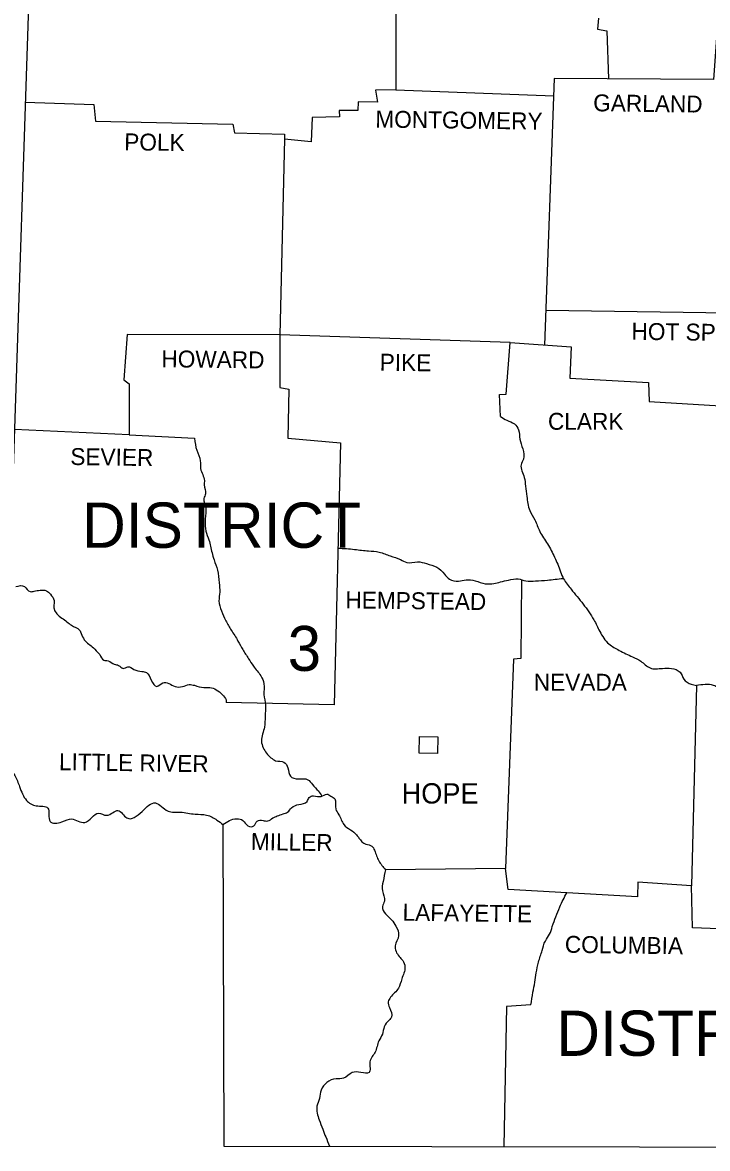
# Model space of a CAD drawing. Extents: x -0.68 to 1.92, y 0 to 0.95.
# Drawn here: x 1.1026 to 1.1814, y 0.5736 to 0.703 of the extents above; entities that cross this region are included whole.
import ezdxf

# ---------------------------------------------------------------- set-up
doc = ezdxf.new("R2010")
doc.units = 0
doc.layers.add('Default', color=7, linetype='Continuous')

msp = doc.modelspace()

# ---------------------------------------------------------------- linework, layer by layer
at = {"layer": 'Default'}
for points in [[(1.09511, 0.81784), (1.10455, 0.74198), (1.10045, 0.61817)], [(1.14558, 0.71393), (1.14552, 0.69525), (1.14321, 0.6952), (1.14342, 0.69385), (1.14122, 0.69387), (1.14116, 0.69286), (1.13901, 0.69286), (1.13906, 0.69216), (1.1359, 0.69206), (1.13582, 0.68928), (1.13274, 0.68957), (1.13222, 0.66711)], [(1.16881, 0.70347), (1.16873, 0.70223), (1.1698, 0.70204), (1.16999, 0.69651)], [(1.19734, 0.70186), (1.18245, 0.7023), (1.18204, 0.69644), (1.16375, 0.69655), (1.16263, 0.66592)], [(1.14552, 0.69525), (1.16368, 0.69454)], [(1.10295, 0.69382), (1.11082, 0.69356), (1.11103, 0.69164), (1.1268, 0.69131), (1.12698, 0.69032), (1.13274, 0.69014), (1.13274, 0.68957)], [(1.16278, 0.66994), (1.18904, 0.66955), (1.18953, 0.67391), (1.19161, 0.67388), (1.19166, 0.67754), (1.20149, 0.67741), (1.20144, 0.6752), (1.20398, 0.67502), (1.20395, 0.67103), (1.20561, 0.67087)], [(1.15867, 0.6662), (1.13222, 0.66711), (1.11466, 0.66714), (1.11427, 0.66192), (1.11489, 0.66148), (1.11487, 0.65562), (1.10171, 0.65622)], [(1.13222, 0.66711), (1.13222, 0.66104), (1.13323, 0.66086), (1.13312, 0.65521), (1.13919, 0.65471), (1.13844, 0.62458), (1.12604, 0.62486)], [(1.15758, 0.65772), (1.15745, 0.66024), (1.1582, 0.66029), (1.15867, 0.6662), (1.16567, 0.66571), (1.16552, 0.66211), (1.17457, 0.66161), (1.17465, 0.65943), (1.18284, 0.65894), (1.18424, 0.65648), (1.18339, 0.65536), (1.1838, 0.65368), (1.2047, 0.65291)], [(1.11487, 0.65562), (1.12241, 0.65521)], [(1.15999, 0.63897), (1.15989, 0.62992), (1.15906, 0.62982), (1.15815, 0.60578)], [(1.18009, 0.62681), (1.1795, 0.60378), (1.17335, 0.60422), (1.1733, 0.60253), (1.16519, 0.603)], [(1.12566, 0.61083), (1.12576, 0.5739), (1.29301, 0.57362)], [(1.16519, 0.603), (1.15846, 0.60339), (1.15815, 0.60578), (1.14433, 0.60565)], [(1.19908, 0.59823), (1.17962, 0.59896), (1.1795, 0.60378)], [(1.16106, 0.59011), (1.15825, 0.58993), (1.15795, 0.57385)]]:
    msp.add_lwpolyline(points, dxfattribs=at)
msp.add_lwpolyline([(1.14822, 0.61903), (1.14827, 0.62097), (1.15037, 0.62092), (1.15032, 0.61898)], close=True, dxfattribs=at)
for points in [[(1.15758, 0.65772), (1.15828, 0.65728), (1.15916, 0.65687), (1.15963, 0.65619), (1.15979, 0.65513), (1.16012, 0.65399), (1.1602, 0.65282), (1.15994, 0.65217), (1.1603, 0.65072), (1.16043, 0.64971), (1.16059, 0.64854), (1.16093, 0.64693), (1.16152, 0.64584), (1.16207, 0.64452), (1.16298, 0.64307), (1.16378, 0.64154), (1.16414, 0.64074), (1.16482, 0.63905), (1.16567, 0.63788), (1.16707, 0.63615), (1.16829, 0.63436), (1.16897, 0.63303), (1.17003, 0.63158), (1.17122, 0.63085), (1.17273, 0.6301), (1.17369, 0.62961), (1.17475, 0.62883), (1.17618, 0.62878), (1.17721, 0.62878), (1.1782, 0.62834), (1.17864, 0.62753), (1.17947, 0.62696), (1.18009, 0.62681)], [(1.12241, 0.65521), (1.12265, 0.65383), (1.12306, 0.65261), (1.12309, 0.65173), (1.12353, 0.65036), (1.1235, 0.64986), (1.12366, 0.64883), (1.12348, 0.64831), (1.12368, 0.64722), (1.12366, 0.64636), (1.12363, 0.64569), (1.12371, 0.64455), (1.12405, 0.64354), (1.12441, 0.64206), (1.12464, 0.64125), (1.12503, 0.64006), (1.12524, 0.63861), (1.12529, 0.63755), (1.12521, 0.63653), (1.1255, 0.63539), (1.12599, 0.63425), (1.12662, 0.63316), (1.12739, 0.63192), (1.12794, 0.63093), (1.12861, 0.62989), (1.12916, 0.62904), (1.13001, 0.62792), (1.13038, 0.62702), (1.13038, 0.62577), (1.13056, 0.62455), (1.13051, 0.62326), (1.13043, 0.62204), (1.13009, 0.62043), (1.1303, 0.61965), (1.13118, 0.61851), (1.13172, 0.61817), (1.13268, 0.61799), (1.13312, 0.61734), (1.13341, 0.61641), (1.13437, 0.61607), (1.13543, 0.61599), (1.13595, 0.61542), (1.13663, 0.6147), (1.13704, 0.61409)], [(1.13889, 0.6426), (1.1408, 0.64245), (1.14241, 0.64227), (1.14363, 0.64214), (1.1449, 0.64169), (1.14607, 0.64128), (1.14679, 0.64094), (1.14801, 0.64102), (1.14907, 0.64081), (1.15024, 0.6404), (1.15112, 0.63962), (1.15169, 0.63902), (1.15273, 0.63879), (1.15361, 0.63895), (1.15465, 0.63884), (1.15582, 0.63851), (1.1568, 0.63853), (1.15758, 0.63871), (1.15849, 0.63892), (1.1596, 0.63905), (1.16046, 0.63884), (1.1616, 0.63882), (1.16295, 0.63892), (1.16478, 0.63912)], [(1.10185, 0.63817), (1.10286, 0.63819), (1.10351, 0.6376), (1.10395, 0.63765), (1.10465, 0.63775), (1.10538, 0.6377), (1.10584, 0.63729), (1.10626, 0.63659), (1.10623, 0.63589), (1.10626, 0.6356), (1.10659, 0.63503), (1.10714, 0.63456), (1.10774, 0.63412), (1.10825, 0.63373), (1.10919, 0.63316), (1.10929, 0.63298), (1.10963, 0.63223), (1.1101, 0.63166), (1.11064, 0.63127), (1.11124, 0.63065), (1.1115, 0.63036), (1.11196, 0.62971), (1.11246, 0.62966), (1.11318, 0.62925), (1.11367, 0.62912), (1.11419, 0.62878), (1.11474, 0.62896), (1.11544, 0.62865), (1.11635, 0.62842), (1.11686, 0.62829), (1.11743, 0.62743), (1.11806, 0.6267), (1.11876, 0.62712), (1.12016, 0.6267), (1.12101, 0.62668), (1.12179, 0.62691), (1.12239, 0.62683), (1.12348, 0.62658), (1.12415, 0.62658), (1.1249, 0.62632), (1.12558, 0.62577), (1.12602, 0.62515), (1.12604, 0.62486)], [(1.18969, 0.62875), (1.18922, 0.62855), (1.18865, 0.62805), (1.18795, 0.62779), (1.18733, 0.62761), (1.18647, 0.62707), (1.18587, 0.6266), (1.18499, 0.62621), (1.18416, 0.62595), (1.18315, 0.62624), (1.18261, 0.62655), (1.18204, 0.62681), (1.18009, 0.62681)], [(1.10045, 0.61817), (1.10174, 0.61646), (1.10229, 0.61519), (1.10309, 0.61361), (1.10421, 0.61299), (1.10553, 0.61273), (1.10579, 0.6112), (1.10716, 0.61114), (1.10828, 0.61148), (1.10978, 0.61107), (1.11139, 0.61213), (1.1123, 0.6119), (1.1136, 0.61244), (1.11463, 0.61159), (1.11637, 0.61234), (1.1179, 0.61332), (1.11935, 0.61239), (1.12078, 0.61226), (1.12247, 0.61203), (1.12379, 0.61192), (1.12498, 0.61135), (1.12566, 0.61083)], [(1.12566, 0.61083), (1.12724, 0.61151), (1.12796, 0.6113), (1.12853, 0.6107), (1.12923, 0.61068), (1.1296, 0.61122), (1.13027, 0.6113), (1.13082, 0.61125), (1.13141, 0.61159), (1.13191, 0.61182), (1.13258, 0.61205), (1.1331, 0.61226), (1.13354, 0.61275), (1.1344, 0.61314), (1.13533, 0.61348), (1.13559, 0.61395), (1.13606, 0.61413), (1.13696, 0.61407), (1.13759, 0.61433), (1.13808, 0.6141), (1.13852, 0.61379), (1.13862, 0.61262), (1.13899, 0.61197), (1.13956, 0.61083), (1.14031, 0.61024), (1.14103, 0.60964), (1.14129, 0.60928), (1.1421, 0.60858), (1.14277, 0.60837), (1.14308, 0.60788), (1.14358, 0.60666), (1.14433, 0.60565)], [(1.14433, 0.60565), (1.14407, 0.6043), (1.14399, 0.60323), (1.14422, 0.60204), (1.14399, 0.60142), (1.14435, 0.60056), (1.14505, 0.59989), (1.14555, 0.59916), (1.14586, 0.59807), (1.14547, 0.59691), (1.14591, 0.59569), (1.14633, 0.59522), (1.14658, 0.59447), (1.14622, 0.59309), (1.14583, 0.59203), (1.14492, 0.59099), (1.14467, 0.59047), (1.1448, 0.5898), (1.14503, 0.58871), (1.14477, 0.58837), (1.1442, 0.5876), (1.14399, 0.58674), (1.14358, 0.58599), (1.14316, 0.58469), (1.14256, 0.58358), (1.14246, 0.58233), (1.14153, 0.58236), (1.14052, 0.58233), (1.13953, 0.58168), (1.13867, 0.58163), (1.13761, 0.58119), (1.13696, 0.58033), (1.13676, 0.57937), (1.13647, 0.57847), (1.13673, 0.57691), (1.13714, 0.57582), (1.13748, 0.57494), (1.13792, 0.57388)], [(1.16106, 0.59011), (1.16129, 0.59156), (1.16152, 0.59273), (1.16168, 0.59379), (1.16194, 0.59504), (1.16235, 0.59636), (1.16272, 0.59745), (1.16321, 0.59823), (1.16352, 0.59914), (1.16393, 0.60025), (1.16438, 0.60137), (1.16519, 0.603)]]:
    msp.add_spline(points, degree=3, dxfattribs=at)

# ---------------------------------------------------------------- texts
for s, height, rotation, p in [('GARLAND', 0.001945, 359.2717, (1.16821, 0.69279)), ('MONTGOMERY', 0.001945, 359.2707, (1.14317, 0.69092)), ('POLK', 0.001945, 359.3233, (1.11431, 0.6883)), ('HOT SPRING', 0.001945, 359.1956, (1.17261, 0.66654)), ('HOWARD', 0.001945, 359.303, (1.11858, 0.66338)), ('PIKE', 0.001945, 359.1737, (1.14367, 0.66299)), ('SEVIER', 0.001945, 359.1815, (1.10811, 0.65215)), ('HEMPSTEAD', 0.001945, 359.2571, (1.13973, 0.63568)), ('LITTLE RIVER', 0.0019451, 359.2076, (1.10681, 0.61708)), ('MILLER', 0.001945, 359.1885, (1.12886, 0.60791)), ('LAFAYETTE', 0.001945, 359.2511, (1.1463, 0.59979)), ('COLUMBIA', 0.001945, 359.2105, (1.16495, 0.59611))]:
    msp.add_text(s, height=height, rotation=rotation, dxfattribs=at).set_placement(p)
for s, height, p in [('CLARK', 0.001945, (1.16302, 0.65619)), ('DISTRICT', 0.005203, (1.10947, 0.64263)), ('3', 0.00516, (1.13311, 0.62849)), ('NEVADA', 0.001945, (1.16139, 0.62621)), ('HOPE', 0.002334, (1.1462, 0.61325)), ('DISTRICT 7', 0.005203, (1.16397, 0.58426))]:
    msp.add_text(s, height=height, dxfattribs=at).set_placement(p)

doc.saveas('drawing.dxf')
